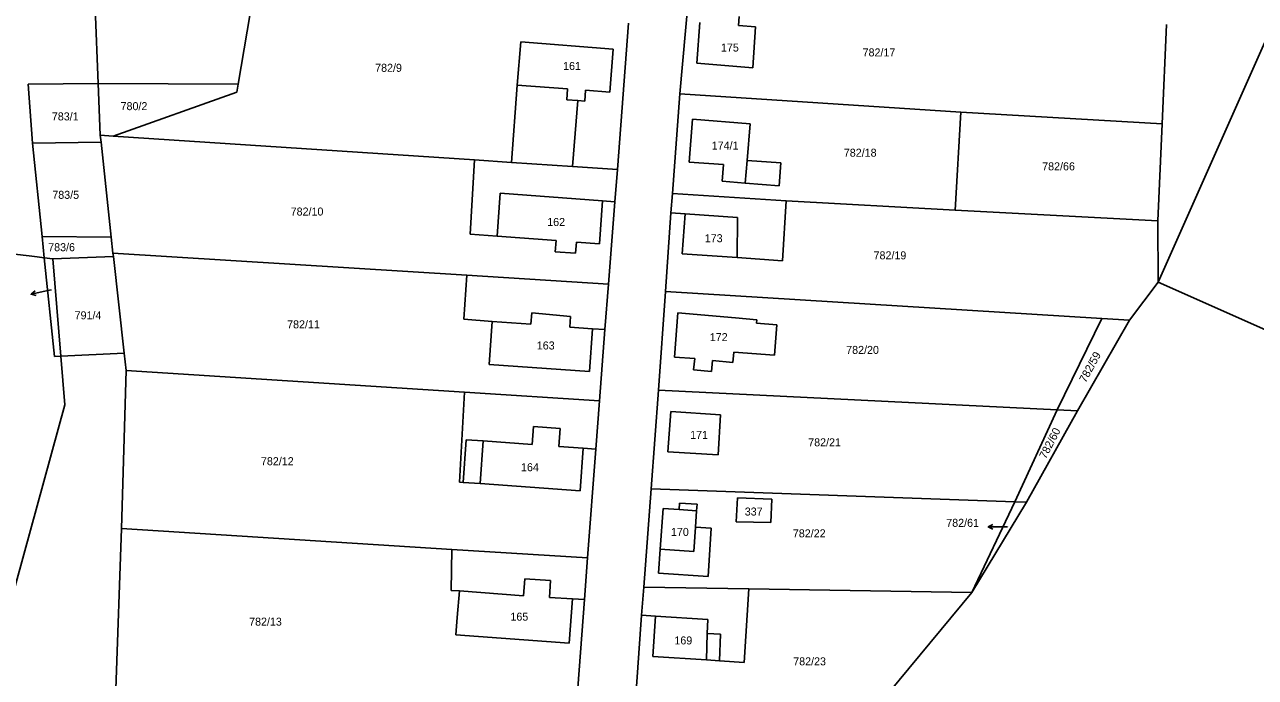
# Model space of a CAD drawing. Extents: x -593358 to -590116, y -1072518 to -1068420.
# Drawn here: x -591964 to -591702.6, y -1070414.2 to -1070275.6 of the extents above; entities that cross this region are included whole.
import ezdxf

# ---------------------------------------------------------------- set-up
doc = ezdxf.new("R2010")
doc.units = 0
for name, color, linetype in [('Parcela KN', 7, 'Continuous'), ('Parcela ZE', 7, 'Continuous'), ('Parcelní číslo', 7, 'Continuous'), ('Parcelní číslo_stavební', 7, 'Continuous'), ('stavby - vnitřní kresba', 7, 'Continuous'), ('Vrstva 16', 7, 'Continuous')]:
    doc.layers.add(name, color=color, linetype=linetype)

msp = doc.modelspace()

# ---------------------------------------------------------------- linework, layer by layer
at = {"layer": 'Parcela KN'}
for p, q in [((-591723.3, -1070330.23), (-591681.52, -1070236.2)), ((-591824.89, -1070290.27), (-591823, -1070269.72)), ((-591948.4, -1070288.04), (-591949.04, -1070272.05)), ((-591916.12, -1070273.19), (-591918.68, -1070288.23)), ((-591812.27, -1070273.86), (-591812.38, -1070275.77)), ((-591838.13, -1070306.3), (-591835.79, -1070275.22)), ((-591821.29, -1070283.76), (-591820.63, -1070275.14)), ((-591812.38, -1070275.77), (-591808.8, -1070276.04)), ((-591808.8, -1070276.04), (-591809.38, -1070284.74)), ((-591721.53, -1070275.53), (-591722.38, -1070296.6)), ((-591858.66, -1070279.24), (-591859.39, -1070288.41)), ((-591839.04, -1070280.8), (-591858.66, -1070279.24)), ((-591839.04, -1070280.8), (-591839.72, -1070289.89)), ((-591809.38, -1070284.74), (-591821.29, -1070283.76)), ((-591947.97, -1070299.04), (-591948.4, -1070288.04)), ((-591918.96, -1070289.9), (-591945.23, -1070299.22)), ((-591918.68, -1070288.23), (-591918.96, -1070289.9)), ((-591859.39, -1070288.41), (-591860.65, -1070304.81)), ((-591844.92, -1070289.51), (-591845.08, -1070291.79)), ((-591839.72, -1070289.89), (-591844.92, -1070289.51)), ((-591846.55, -1070291.69), (-591847.64, -1070305.67)), ((-591845.08, -1070291.79), (-591846.55, -1070291.69)), ((-591826.46, -1070311.39), (-591824.89, -1070290.27)), ((-591765.18, -1070294.15), (-591824.89, -1070290.27)), ((-591765.18, -1070294.15), (-591766.36, -1070314.99)), ((-591722.38, -1070296.6), (-591765.18, -1070294.15)), ((-591822.16, -1070295.67), (-591822.89, -1070304.73)), ((-591809.96, -1070296.6), (-591822.16, -1070295.67)), ((-591810.58, -1070304.39), (-591809.96, -1070296.6)), ((-591723.35, -1070317.19), (-591722.38, -1070296.6)), ((-591947.97, -1070299.04), (-591945.23, -1070299.22)), ((-591947.81, -1070300.54), (-591947.97, -1070299.04)), ((-591945.23, -1070299.22), (-591868.51, -1070304.29)), ((-591945.65, -1070320.67), (-591947.81, -1070300.54)), ((-591869.44, -1070320.03), (-591868.51, -1070304.29)), ((-591868.51, -1070304.29), (-591860.65, -1070304.81)), ((-591860.65, -1070304.81), (-591847.64, -1070305.67)), ((-591847.64, -1070305.67), (-591838.13, -1070306.3)), ((-591822.89, -1070304.73), (-591815.59, -1070305.28)), ((-591815.59, -1070305.28), (-591815.85, -1070308.81)), ((-591803.38, -1070304.91), (-591810.58, -1070304.39)), ((-591803.79, -1070309.76), (-591803.38, -1070304.91)), ((-591838.66, -1070313.18), (-591838.13, -1070306.3)), ((-591815.85, -1070308.81), (-591810.99, -1070309.19)), ((-591810.99, -1070309.19), (-591803.79, -1070309.76)), ((-591841.28, -1070312.98), (-591841.96, -1070322.08)), ((-591841.28, -1070312.98), (-591838.66, -1070313.18)), ((-591840.01, -1070330.65), (-591838.66, -1070313.18)), ((-591826.75, -1070315.49), (-591826.46, -1070311.39)), ((-591826.46, -1070311.39), (-591802.31, -1070312.94)), ((-591803.05, -1070325.71), (-591802.31, -1070312.94)), ((-591802.31, -1070312.94), (-591766.36, -1070314.99)), ((-591827.92, -1070332.23), (-591826.75, -1070315.49)), ((-591826.75, -1070315.49), (-591823.71, -1070315.71)), ((-591823.71, -1070315.71), (-591824.34, -1070324.23)), ((-591766.36, -1070314.99), (-591723.35, -1070317.19)), ((-591723.3, -1070330.23), (-591723.35, -1070317.19)), ((-591945.28, -1070324.07), (-591945.65, -1070320.67)), ((-591869.44, -1070320.03), (-591863.69, -1070320.46)), ((-591863.69, -1070320.46), (-591851.15, -1070321.4)), ((-591986.41, -1070321.96), (-591963.11, -1070324.68)), ((-591851.32, -1070323.78), (-591851.15, -1070321.4)), ((-591847.03, -1070324.12), (-591851.32, -1070323.78)), ((-591846.84, -1070321.72), (-591847.03, -1070324.12)), ((-591846.84, -1070321.72), (-591841.96, -1070322.08)), ((-591963.11, -1070324.68), (-591961.41, -1070324.88)), ((-591961.41, -1070324.88), (-591959.86, -1070325.06)), ((-591959.86, -1070325.06), (-591958.03, -1070325.27)), ((-591958.03, -1070325.27), (-591945.2, -1070324.82)), ((-591958.03, -1070325.27), (-591956.36, -1070345.96)), ((-591870.08, -1070328.77), (-591945.28, -1070324.07)), ((-591945.28, -1070324.07), (-591945.2, -1070324.82)), ((-591945.2, -1070324.82), (-591942.87, -1070345.34)), ((-591824.34, -1070324.23), (-591812.7, -1070325.04)), ((-591812.7, -1070325.04), (-591803.05, -1070325.71)), ((-591870.77, -1070338.13), (-591870.08, -1070328.77)), ((-591840.01, -1070330.65), (-591870.08, -1070328.77)), ((-591840.77, -1070340.32), (-591840.01, -1070330.65)), ((-591729.34, -1070338.34), (-591723.3, -1070330.23)), ((-591723.3, -1070330.23), (-591671.97, -1070353.08)), ((-591829.4, -1070353.17), (-591827.92, -1070332.23)), ((-591827.92, -1070332.23), (-591735.24, -1070337.97)), ((-591825.31, -1070336.74), (-591826.01, -1070346.16)), ((-591813.01, -1070337.85), (-591825.31, -1070336.74)), ((-591864.72, -1070338.57), (-591870.77, -1070338.13)), ((-591865.36, -1070347.7), (-591864.72, -1070338.57)), ((-591808.51, -1070338.26), (-591813.01, -1070337.85)), ((-591808.57, -1070338.95), (-591808.51, -1070338.26)), ((-591804.26, -1070339.28), (-591808.57, -1070338.95)), ((-591804.76, -1070345.78), (-591804.26, -1070339.28)), ((-591744.71, -1070357.38), (-591735.24, -1070337.97)), ((-591729.34, -1070338.34), (-591740.37, -1070357.6)), ((-591735.24, -1070337.97), (-591729.34, -1070338.34)), ((-591843.4, -1070340.13), (-591844.05, -1070349.2)), ((-591843.4, -1070340.13), (-591840.77, -1070340.32)), ((-591841.95, -1070355.42), (-591840.77, -1070340.32)), ((-591956.36, -1070345.96), (-591955.53, -1070356.27)), ((-591942.87, -1070345.34), (-591942.45, -1070349.03)), ((-591826.01, -1070346.16), (-591821.71, -1070346.48)), ((-591821.71, -1070346.48), (-591821.94, -1070348.85)), ((-591818.16, -1070349.22), (-591817.93, -1070346.91)), ((-591817.93, -1070346.91), (-591813.6, -1070347.33)), ((-591813.6, -1070347.33), (-591813.43, -1070345.11)), ((-591813.43, -1070345.11), (-591804.76, -1070345.78)), ((-591943.49, -1070382.54), (-591942.45, -1070349.03)), ((-591942.45, -1070349.03), (-591870.64, -1070353.6)), ((-591844.05, -1070349.2), (-591865.36, -1070347.7)), ((-591821.94, -1070348.85), (-591818.16, -1070349.22)), ((-591870.64, -1070353.6), (-591871.65, -1070372.71)), ((-591870.64, -1070353.6), (-591841.95, -1070355.42)), ((-591830.95, -1070374.12), (-591829.4, -1070353.17)), ((-591744.71, -1070357.38), (-591829.4, -1070353.17)), ((-591955.53, -1070356.27), (-591967.28, -1070399.16)), ((-591842.73, -1070365.69), (-591841.95, -1070355.42)), ((-591826.81, -1070357.74), (-591827.45, -1070366.3)), ((-591816.21, -1070358.44), (-591826.81, -1070357.74)), ((-591753.7, -1070376.87), (-591744.71, -1070357.38)), ((-591751.25, -1070376.96), (-591740.37, -1070357.6)), ((-591740.37, -1070357.6), (-591744.71, -1070357.38)), ((-591816.72, -1070366.94), (-591816.21, -1070358.44)), ((-591845.37, -1070365.49), (-591846.04, -1070374.53)), ((-591845.37, -1070365.49), (-591842.73, -1070365.69)), ((-591844.49, -1070388.8), (-591842.73, -1070365.69)), ((-591827.45, -1070366.3), (-591816.72, -1070366.94)), ((-591870.9, -1070372.76), (-591871.65, -1070372.71)), ((-591867.3, -1070373.01), (-591870.9, -1070372.76)), ((-591846.04, -1070374.53), (-591867.3, -1070373.01)), ((-591832.54, -1070395.01), (-591830.95, -1070374.12)), ((-591830.95, -1070374.12), (-591753.7, -1070376.87)), ((-591812.92, -1070381.1), (-591812.65, -1070376.07)), ((-591812.65, -1070376.07), (-591805.36, -1070376.35)), ((-591828.4, -1070378.31), (-591829.02, -1070386.91)), ((-591825.02, -1070378.55), (-591828.4, -1070378.31)), ((-591824.92, -1070377.16), (-591825.02, -1070378.55)), ((-591821.2, -1070377.41), (-591824.92, -1070377.16)), ((-591821.54, -1070382.26), (-591821.3, -1070378.83)), ((-591821.3, -1070378.83), (-591821.2, -1070377.41)), ((-591805.36, -1070376.35), (-591805.55, -1070381.27)), ((-591762.84, -1070396.11), (-591753.7, -1070376.87)), ((-591762.84, -1070396.11), (-591751.25, -1070376.96)), ((-591753.7, -1070376.87), (-591751.25, -1070376.96)), ((-591805.55, -1070381.27), (-591812.92, -1070381.1)), ((-591944.66, -1070416.69), (-591943.49, -1070382.54)), ((-591943.49, -1070382.54), (-591873.28, -1070386.98)), ((-591818.22, -1070382.45), (-591821.54, -1070382.26)), ((-591818.83, -1070392.73), (-591818.22, -1070382.45)), ((-591873.43, -1070395.69), (-591873.28, -1070386.98)), ((-591873.28, -1070386.98), (-591844.49, -1070388.8)), ((-591845.14, -1070397.66), (-591844.49, -1070388.8)), ((-591829.02, -1070386.91), (-591829.39, -1070392.04)), ((-591829.39, -1070392.04), (-591818.83, -1070392.73)), ((-591871.69, -1070395.82), (-591873.43, -1070395.69)), ((-591872.14, -1070401.43), (-591871.69, -1070395.82)), ((-591832.98, -1070400.98), (-591832.54, -1070395.01)), ((-591810.19, -1070395.36), (-591832.54, -1070395.01)), ((-591811.18, -1070411), (-591810.19, -1070395.36)), ((-591762.84, -1070396.11), (-591810.19, -1070395.36)), ((-591785.4, -1070423.3), (-591762.84, -1070396.11)), ((-591847.7, -1070397.5), (-591848.41, -1070406.87)), ((-591847.7, -1070397.5), (-591845.14, -1070397.66)), ((-591846.92, -1070421.75), (-591845.14, -1070397.66)), ((-591872.42, -1070405.1), (-591872.14, -1070401.43)), ((-591834.74, -1070425.2), (-591832.98, -1070400.98)), ((-591830.01, -1070401.17), (-591832.98, -1070400.98)), ((-591830.01, -1070401.17), (-591830.61, -1070409.72)), ((-591848.41, -1070406.87), (-591872.42, -1070405.1)), ((-591830.61, -1070409.72), (-591819.22, -1070410.47)), ((-591819.22, -1070410.47), (-591816.46, -1070410.65)), ((-591816.46, -1070410.65), (-591811.18, -1070411))]:
    msp.add_line(p, q, dxfattribs=at)
at = {"layer": 'Parcela ZE'}
for p, q in [((-591963.32, -1070288.18), (-591948.4, -1070288.04)), ((-591962.4, -1070300.72), (-591963.32, -1070288.18)), ((-591948.4, -1070288.04), (-591918.68, -1070288.23)), ((-591947.81, -1070300.54), (-591962.4, -1070300.72)), ((-591960.33, -1070320.55), (-591962.4, -1070300.72)), ((-591960.33, -1070320.55), (-591945.65, -1070320.67)), ((-591959.86, -1070325.06), (-591960.33, -1070320.55)), ((-591957.69, -1070346.02), (-591959.86, -1070325.06)), ((-591957.69, -1070346.02), (-591956.36, -1070345.96)), ((-591956.36, -1070345.96), (-591942.87, -1070345.34))]:
    msp.add_line(p, q, dxfattribs=at)
at = {"layer": 'stavby - vnitřní kresba'}
for p, q in [((-591848.7, -1070289.22), (-591859.39, -1070288.41)), ((-591848.87, -1070291.52), (-591848.7, -1070289.22)), ((-591846.55, -1070291.69), (-591848.87, -1070291.52)), ((-591810.58, -1070304.39), (-591810.99, -1070309.19)), ((-591863.03, -1070311.35), (-591863.69, -1070320.46)), ((-591863.03, -1070311.35), (-591841.28, -1070312.98)), ((-591812.59, -1070316.53), (-591823.71, -1070315.71)), ((-591812.59, -1070316.53), (-591812.7, -1070325.04)), ((-591856.33, -1070336.78), (-591856.5, -1070339.17)), ((-591856.33, -1070336.78), (-591848.12, -1070337.54)), ((-591864.72, -1070338.57), (-591856.5, -1070339.17)), ((-591848.12, -1070337.54), (-591848.24, -1070339.78)), ((-591848.24, -1070339.78), (-591843.4, -1070340.13)), ((-591856.24, -1070364.72), (-591855.97, -1070360.88)), ((-591855.97, -1070360.88), (-591850.27, -1070361.29)), ((-591850.27, -1070361.29), (-591850.55, -1070365.12)), ((-591870.9, -1070372.76), (-591870.25, -1070363.72)), ((-591870.25, -1070363.72), (-591866.67, -1070363.97)), ((-591866.67, -1070363.97), (-591867.3, -1070373.01)), ((-591866.67, -1070363.97), (-591856.24, -1070364.72)), ((-591850.55, -1070365.12), (-591845.37, -1070365.49)), ((-591825.02, -1070378.55), (-591821.3, -1070378.83)), ((-591821.54, -1070382.26), (-591821.9, -1070387.41)), ((-591821.9, -1070387.41), (-591829.02, -1070386.91)), ((-591858.09, -1070396.85), (-591857.82, -1070393.24)), ((-591857.82, -1070393.24), (-591852.34, -1070393.58)), ((-591852.34, -1070393.58), (-591852.57, -1070397.2)), ((-591871.69, -1070395.82), (-591858.09, -1070396.85)), ((-591852.57, -1070397.2), (-591847.7, -1070397.5)), ((-591818.95, -1070401.88), (-591830.01, -1070401.17)), ((-591818.95, -1070401.88), (-591819.04, -1070404.83)), ((-591819.04, -1070404.83), (-591819.22, -1070410.47)), ((-591819.04, -1070404.83), (-591816.26, -1070404.99)), ((-591816.26, -1070404.99), (-591816.46, -1070410.65))]:
    msp.add_line(p, q, dxfattribs=at)
at = {"layer": 'Vrstva 16'}
for p, q in [((-591962.673, -1070332.799), (-591959.74, -1070332.17)), ((-591958.43, -1070331.89), (-591959.74, -1070332.17)), ((-591759.37, -1070382.201), (-591756.37, -1070382.2)), ((-591755.24, -1070382.2), (-591756.37, -1070382.2))]:
    msp.add_line(p, q, dxfattribs=at)
for points in [[(-591961.591, -1070333.078), (-591962.673, -1070332.799), (-591961.8, -1070332.1)], [(-591758.37, -1070382.7), (-591759.37, -1070382.201), (-591758.37, -1070381.7)]]:
    msp.add_lwpolyline(points, dxfattribs=at)

# ---------------------------------------------------------------- texts
at = {"layer": 'Parcelní číslo'}
for s, height, p in [('782/17', 1.7, (-591786.044, -1070282.31)), ('782/9', 1.7, (-591889.593, -1070285.58)), ('780/2', 1.7, (-591943.66, -1070293.72)), ('783/1', 1.7, (-591958.259, -1070295.9)), ('782/18', 1.7, (-591790.035, -1070303.61)), ('782/66', 1.7, (-591747.903, -1070306.5)), ('783/5', 1.7, (-591958.164, -1070312.55)), ('782/10', 1.7, (-591907.531, -1070316.1)), ('783/6', 1.7, (-591959.037, -1070323.67)), ('782/19', 1.7, (-591783.715, -1070325.4)), ('791/4', 1.7, (-591953.425, -1070338.13)), ('782/11', 1.7, (-591908.287, -1070340.05)), ('782/20', 1.7, (-591789.533, -1070345.48)), ('782/21', 1.7, (-591797.598, -1070365.1)), ('782/12', 1.7, (-591913.848, -1070369.11)), ('782/22', 1.7, (-591800.86, -1070384.43)), ('782/61', 0.1, (-591755.466, -1070382.2)), ('782/13', 1.7, (-591916.362, -1070403.18)), ('782/23', 1.7, (-591800.783, -1070411.61))]:
    msp.add_text(s, height=height, dxfattribs=at).set_placement(p)
for s, height, rotation, p in [('857/61', 0.1, 277.65535, (-591958.46, -1070331.668)), ('782/59', 1.7, 61.42108, (-591738.663, -1070351.724)), ('782/60', 1.7, 62.68158, (-591747.122, -1070367.91))]:
    msp.add_text(s, height=height, rotation=rotation, dxfattribs=at).set_placement(p)
at = {"layer": 'Parcelní číslo_stavební'}
for s, p in [('175', (-591816.133, -1070281.28)), ('161', (-591849.668, -1070285.19)), ('174/1', (-591818.097, -1070302.09)), ('162', (-591853.04, -1070318.32)), ('173', (-591819.573, -1070321.76)), ('172', (-591818.51, -1070342.77)), ('163', (-591855.253, -1070344.54)), ('171', (-591822.678, -1070363.53)), ('164', (-591858.606, -1070370.39)), ('337', (-591811.078, -1070379.8)), ('170', (-591826.753, -1070384.13)), ('165', (-591860.853, -1070402.12)), ('169', (-591826.026, -1070407.17))]:
    msp.add_text(s, height=1.7, dxfattribs=at).set_placement(p)
at = {"layer": 'Vrstva 16'}
msp.add_text('782/61', height=1.7, dxfattribs=at).set_placement((-591768.277, -1070382.2))

doc.saveas('drawing.dxf')
